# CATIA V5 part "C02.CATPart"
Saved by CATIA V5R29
Part number: C02
Source: Unknown
Bounding box of the stored display mesh (mm): x -32.98 to 32.98, y -100 to 300, z -33 to 33
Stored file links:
  C:\Users\Administrator\Desktop\프로젝트\Boxfold\TapeCutter\C02.CATPart
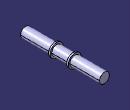
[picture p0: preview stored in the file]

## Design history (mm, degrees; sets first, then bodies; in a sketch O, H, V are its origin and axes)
Body1 (main body)
  Solid1 "PartBody": solid without history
